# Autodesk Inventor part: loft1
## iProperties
Shininess: 64.0
Length Units: 11269
Angle Units: 11279
Time Units: 11290
Mass Units: 11283
Length Display Precision: 3
Angle Display Precision: 2
Compacted: True
Part Number: loft1
Document SubType Name: Modeling
Created: 2002-12
Designer: deepak
Density: 0.0
Volumn: 0.0
Area: 0.0
PropertySet Name: Model Information
Control State: 0
Master: False
Checked Out: False
Author: deepak
